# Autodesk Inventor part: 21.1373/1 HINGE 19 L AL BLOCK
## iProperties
Created: 2007-01
Part Number: 21.1373/1 HINGE 19 L AL BLOCK
Document SubType Name: Modeling
Designer: Andy Moles
Material: Aluminum-6061
Density: 2.71 g/cm^3
Mass: 18.3877 g
Surface Area: 42.4483 cm^2
Volume: 6.78512 cm^3
Author: Andy Moles
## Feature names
1. Extrusion1
2. Hole1
